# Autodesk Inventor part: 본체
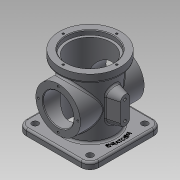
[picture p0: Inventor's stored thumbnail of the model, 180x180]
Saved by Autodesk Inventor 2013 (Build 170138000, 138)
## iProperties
Created: 2021-03
Part Number: 본체
Material: 일반
Document SubType Name: Modeling
Designer: hana-cad24
Density: 1 g/cm^3
Author: hana-cad24
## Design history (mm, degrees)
sketch "스케치1"
  geometry: L1 (-57, -57)-(57, -57); L2 (57, -57)-(57, 57); L3 (57, 57)-(-57, 57); L4 (-57, 57)-(-57, -57); L5 (-57, -57)-(57, 57); L6 (57, -57)-(-57, 57); 1 further point
  constraints: 12 end point, 2 midpoint, 2 parallel, 1 horizontal, 1 perpendicular
  dimensions: "d0" = 114 distance of L3.end L2.end; "d1" = 114 distance of L2.end L1.end
extrude "돌출1" new body sketch "스케치1" distance "d2" = 10; taper "d3" = 0 deg
fillet "모깎기1" dims "d4" = 14
sketch "스케치2"
  geometry: A1 r 14 centre (43, 43) between (57, 43) and (43, 57) reference; A2 r 14 centre (-43, 43) between (-43, 57) and (-57, 43) reference; A3 r 14 centre (-43, -43) between (-57, -43) and (-43, -57) reference; A4 r 14 centre (43, -43) between (43, -57) and (57, -43) reference; 1 further point
hole "구멍1" sketch "스케치2" at (-43, 43), (43, 43), (43, -43), (-43, -43) diameter "d5" = 10; stored, may be unused: countersink angle "d9" = 90 deg, drill point angle "d11" = 118 deg; dims "d6" = 6, "d7" = 4, "d8" = 2, "d10" = 8
sketch "스케치4"
  geometry: C1 r 38 at (0, 0); 1 further point
  constraints: 1 centre point, 1 coincident
  dimensions: "d13" = 76 diameter of C1
extrude "돌출2" join sketch "스케치4" distance "d14" = 88; taper "d15" = 0 deg
sketch "스케치5"
  geometry: C1 r 38 at (0, 0) reference; C2 r 48 at (0, 0)
  constraints: 1 centre point, 1 coincident
  dimensions: "d16" = 96 diameter of C2
extrude "돌출3" join sketch "스케치5" distance "d17" = 13; taper "d18" = 0 deg
sketch "스케치6"
  geometry: C1 r 48 at (0, 0) reference
hole "구멍2" sketch "스케치6" at (0, 0) diameter "d19" = 66; stored, may be unused: countersink angle "d23" = 90 deg, drill point angle "d25" = 118 deg; dims "d20" = 6, "d21" = 74, "d22" = 7, "d24" = 8
sketch "스케치7"
  geometry: L1 (48, 98)-(38, 98) reference; L2 (38, 98)-(38, 10) reference; L3 (38, 10)-(57, 10) reference; L4 (57, 10)-(57, 0) reference; L5 (57, 0)-(33, 0) reference; L6 (33, 0)-(33, 104) reference; L7 (33, 104)-(37, 104) reference; L8 (37, 104)-(37, 111) reference; L9 (37, 111)-(48, 111) reference; L10 (48, 111)-(48, 98) reference; L11 (-38, 98)-(-48, 98) reference; L12 (-48, 98)-(-48, 111) reference; L13 (-48, 111)-(-37, 111) reference; L14 (-37, 111)-(-37, 104) reference; L15 (-37, 104)-(-33, 104) reference; L16 (-33, 104)-(-33, 0) reference; L17 (-33, 0)-(-57, 0) reference; L18 (-57, 0)-(-57, 10) reference; L19 (-57, 10)-(-38, 10) reference; L20 (-38, 10)-(-38, 98) reference; L21 (-50, 89)-(50, 89); L22 (50, 89)-(50, 54); L23 (50, 54)-(-50, 54); L24 (-50, 54)-(-50, 89); 2 further points
  constraints: 8 end point, 2 parallel, 1 horizontal, 1 midpoint, 1 perpendicular, 1 vertical alignment
  dimensions: "d26" = 54 distance from line of point (0, 0) L23; "d27" = 100 distance of L21.start L21.end; "d28" = 70 diameter of L21 L23
revolve "회전1" sketch "스케치7" stored, may be unused: angle "d29" = 90 deg
sketch "스케치8"
  geometry: C1 r 35 at (0, 0) reference; C2 r 24 at (0, 0); 1 further point
  constraints: 1 centre point, 1 coincident
  dimensions: "d30" = 48 diameter of C2
extrude "돌출4" cut sketch "스케치8" stored distance "d31" = 13; taper "d32" = 0 deg
sketch "스케치9"
  geometry: C1 r 33 at (0, 0) reference
extrude "돌출5" cut sketch "스케치9" stored distance "d33" = 13; taper "d34" = 0 deg
sketch "스케치10"
  geometry: C1 r 24 at (0, 0) reference; 2 further points
  constraints: 1 vertical alignment
  dimensions: "d35" = 31 distance of point (0, 31) C1.centre
hole "구멍3" sketch "스케치10" at (0, 31) diameter "d36" = 3.242; stored, may be unused: countersink angle "d40" = 90 deg, drill point angle "d42" = 118 deg; dims "d37" = 6, "d38" = 74, "d39" = 7, "d41" = 8
sketch "스케치11"
  geometry: C1 r 37 at (0, 0) reference; 1 further point
  constraints: 1 horizontal alignment
  dimensions: "d46" = 42 distance of C1.centre point (42, 0)
hole "구멍4" sketch "스케치11" at (42, 0) diameter "d47" = 3.242; stored, may be unused: countersink angle "d51" = 90 deg, drill point angle "d53" = 118 deg; dims "d48" = 6, "d49" = 74, "d50" = 7, "d52" = 8
node "작업 평면1"
sketch "스케치12"
  geometry: L1 (-50, 19)-(-50, 89) reference; L2 (50, 19)-(50, 89) reference; L3 (-38, 10)-(38, 10) reference; L4 (-7, 41)-(-7, 70); L5 (7, 41)-(7, 70); L6 (48, 111)-(-48, 111) reference; A1 r 7 centre (0, 41) between (-7, 41) and (7, 41); A2 r 7 centre (0, 70) between (7, 70) and (-7, 70); 3 further points
  constraints: 4 end point, 4 point on circle, 3 tangent, 2 centre point, 2 midpoint, 1 parallel, 1 perpendicular, 1 vertical alignment
  dimensions: "d61" = 14 distance between parallel lines of L4 L5; "d65" = 7 radius of A1; "d68" = 43 dimension on A1 A2; "d69" = 13 vertical distance of A1.centre point (-50, 54)
extrude "돌출6" join sketch "스케치12" stored distance "d70" = 13; taper "d71" = 0 deg
feature "면 기울기1" dims angle "d72" = 15 deg
sketch "스케치13"
  geometry: A1 r 7 centre (0, -41) between (7, -41) and (-7, -41) reference; A2 r 7 centre (0, -70) between (-7, -70) and (7, -70) reference; 1 further point
hole "구멍5" sketch "스케치13" at (0, -41), (0, -70) diameter "d73" = 4.134; stored, may be unused: countersink angle "d77" = 90 deg, drill point angle "d79" = 118 deg; dims "d74" = 8, "d75" = 74, "d76" = 7, "d78" = 10
node "작업 평면2"
sketch "스케치14"
  geometry: C1 r 50 at (0, 0); 1 further point
  constraints: 1 centre point, 1 coincident, 1 other
  dimensions: "d81" = 100 diameter of C1
feature "엠보싱1" sketch "스케치14" dims "d0" = 114, "d1" = 114, "d82" = 0.5, "d83" = 0
fillet "모깎기2" dims "d84" = 3
fillet "모깎기3" dims "d85" = 3
fillet "모깎기4" dims "d86" = 3
fillet "모깎기5" dims "d87" = 3
fillet "모깎기6" dims "d88" = 3
chamfer "모따기1" distance "d89" = 1; stored, may be unused: second distance "d90" = 2, angle "d91" = 45 deg
node "솔리드1"
pattern_circular "원형 패턴1" dims angle "d44" = 360 deg
mirror "대칭1"
pattern_circular "원형 패턴2" dims angle "d55" = 360 deg
node "절단 모서리 투영1"
other parameters: "d57" = 55, "d80" = 3
